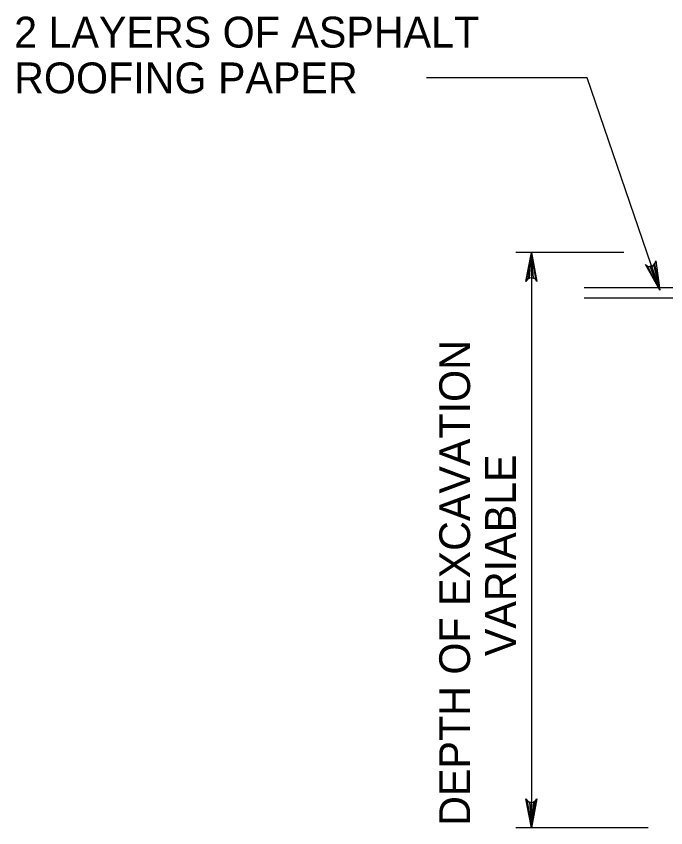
# Model space of a CAD drawing. Extents: x 1.32 to 7.47, y -3.56 to 5.14.
# Drawn here: x 1.319 to 2.583, y 3.447 to 5.026 of the extents above; entities that cross this region are included whole.
import ezdxf

# ---------------------------------------------------------------- set-up
doc = ezdxf.new("R2010")
doc.units = 0
for name, color, linetype in [('DETL-DIMS', 7, 'Continuous'), ('DETL-LINE', 7, 'Continuous'), ('DETL-NOTE', 7, 'Continuous')]:
    doc.layers.add(name, color=color, linetype=linetype)

msp = doc.modelspace()

# ---------------------------------------------------------------- linework, layer by layer
at = {"layer": 'DETL-DIMS'}
for p, q in [((2.4306, 4.9059), (2.1173, 4.9059)), ((2.572, 4.493), (2.4306, 4.9059)), ((2.5015, 4.5663), (2.2915, 4.5663)), ((2.3218, 4.5663), (2.3218, 3.4469)), ((2.5491, 3.4469), (2.2915, 3.4469))]:
    msp.add_line(p, q, dxfattribs=at)
for points in [[(2.3218, 4.5663), (2.3324, 4.5098), (2.3294, 4.5142), (2.3256, 4.5164), (2.3218, 4.5171), (2.3181, 4.5164), (2.3143, 4.5142), (2.3112, 4.5098), (2.3218, 4.5663), (2.3143, 4.5142), (2.3181, 4.5164), (2.3218, 4.5663), (2.3218, 4.5171), (2.3256, 4.5164), (2.3218, 4.5663), (2.3294, 4.5142)], [(2.572, 4.493), (2.5437, 4.543), (2.548, 4.5398), (2.5523, 4.5389), (2.5561, 4.5395), (2.5594, 4.5414), (2.5623, 4.5447), (2.5637, 4.5498), (2.572, 4.493), (2.5623, 4.5447), (2.5594, 4.5414), (2.572, 4.493), (2.5561, 4.5395), (2.5523, 4.5389), (2.572, 4.493), (2.548, 4.5398)], [(2.3218, 3.4469), (2.3112, 3.5034), (2.3143, 3.499), (2.3181, 3.4968), (2.3218, 3.4961), (2.3256, 3.4968), (2.3294, 3.499), (2.3324, 3.5034), (2.3218, 3.4469), (2.3294, 3.499), (2.3256, 3.4968), (2.3218, 3.4469), (2.3218, 3.4961), (2.3181, 3.4968), (2.3218, 3.4469), (2.3143, 3.499)]]:
    msp.add_lwpolyline(points, dxfattribs=at)
at = {"layer": 'DETL-LINE'}
for p, q in [((5.1877, 4.4974), (2.4245, 4.4974)), ((5.1837, 4.4772), (2.4245, 4.4772))]:
    msp.add_line(p, q, dxfattribs=at)

# ---------------------------------------------------------------- texts
at = {"layer": 'DETL-NOTE'}
for s, p in [('2 LAYERS OF ASPHALT', (1.3149, 4.9649)), ('ROOFING PAPER', (1.3149, 4.8759))]:
    msp.add_text(s, height=0.06, dxfattribs=at).set_placement(p)
for s, p in [('DEPTH OF EXCAVATION', (2.2024, 3.4506)), ('VARIABLE', (2.2915, 3.7808))]:
    msp.add_text(s, height=0.06, rotation=90, dxfattribs=at).set_placement(p)

doc.saveas('drawing.dxf')
